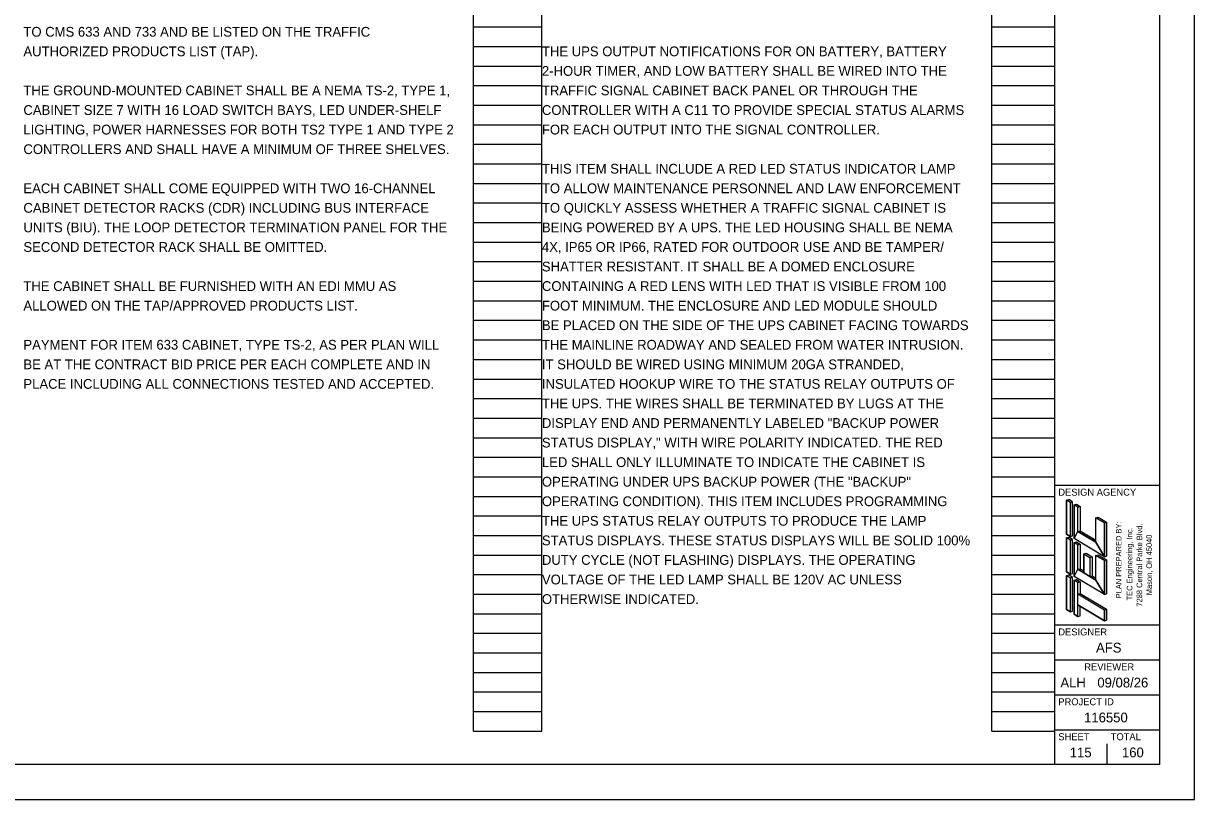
# Model space of a CAD drawing. Extents: x 0 to 34, y 0 to 36.2.
# Drawn here: x 17.24 to 34, y 0 to 11.11 of the extents above; entities that cross this region are included whole.
import ezdxf

# ---------------------------------------------------------------- set-up
doc = ezdxf.new("R2010")
doc.units = 0
for name, color, linetype in [('Default', 7, 'Continuous'), ('SH_Border', 7, 'Continuous'), ('SH_Cut_Line', 7, 'Continuous'), ('SH_Data', 7, 'Continuous'), ('SH_Text', 7, 'Continuous')]:
    doc.layers.add(name, color=color, linetype=linetype)

msp = doc.modelspace()

# ---------------------------------------------------------------- linework, layer by layer
at = {"layer": 'SH_Border'}
for p, q in [((32, 0.5), (32, 21.5)), ((32, 4.5), (33.5, 4.5)), ((32, 2.5), (33.5, 2.5)), ((32, 2), (33.5, 2)), ((32, 1.5), (33.5, 1.5)), ((32, 1), (33.5, 1))]:
    msp.add_line(p, q, dxfattribs=at)
msp.add_lwpolyline([(1.5, 21.5), (33.5, 21.5), (33.5, 0.5), (1.5, 0.5)], close=True, dxfattribs=at)
at = {"layer": 'SH_Cut_Line'}
msp.add_lwpolyline([(0, 0), (34, 0), (34, 22), (0, 22)], close=True, dxfattribs=at)
at = {"layer": 'SH_Data'}
for p, q in [((23.68, 0.98), (23.68, 21.14)), ((24.66, 0.98), (24.66, 21.14)), ((31.1, 0.98), (31.1, 21.14)), ((32, 0.98), (32, 21.14)), ((23.68, 11.06), (24.66, 11.06)), ((31.1, 11.06), (32, 11.06)), ((23.68, 10.78), (24.66, 10.78)), ((31.1, 10.78), (32, 10.78)), ((23.68, 10.5), (24.66, 10.5)), ((31.1, 10.5), (32, 10.5)), ((23.68, 10.22), (24.66, 10.22)), ((31.1, 10.22), (32, 10.22)), ((23.68, 9.94), (24.66, 9.94)), ((31.1, 9.94), (32, 9.94)), ((23.68, 9.66), (24.66, 9.66)), ((31.1, 9.66), (32, 9.66)), ((23.68, 9.38), (24.66, 9.38)), ((31.1, 9.38), (32, 9.38)), ((23.68, 9.1), (24.66, 9.1)), ((31.1, 9.1), (32, 9.1)), ((23.68, 8.82), (24.66, 8.82)), ((31.1, 8.82), (32, 8.82)), ((23.68, 8.54), (24.66, 8.54)), ((31.1, 8.54), (32, 8.54)), ((23.68, 8.26), (24.66, 8.26)), ((31.1, 8.26), (32, 8.26)), ((23.68, 7.98), (24.66, 7.98)), ((31.1, 7.98), (32, 7.98)), ((23.68, 7.7), (24.66, 7.7)), ((31.1, 7.7), (32, 7.7)), ((23.68, 7.42), (24.66, 7.42)), ((31.1, 7.42), (32, 7.42)), ((23.68, 7.14), (24.66, 7.14)), ((31.1, 7.14), (32, 7.14)), ((23.68, 6.86), (24.66, 6.86)), ((31.1, 6.86), (32, 6.86)), ((23.68, 6.58), (24.66, 6.58)), ((31.1, 6.58), (32, 6.58)), ((23.68, 6.3), (24.66, 6.3)), ((31.1, 6.3), (32, 6.3)), ((23.68, 6.02), (24.66, 6.02)), ((31.1, 6.02), (32, 6.02)), ((23.68, 5.74), (24.66, 5.74)), ((31.1, 5.74), (32, 5.74)), ((23.68, 5.46), (24.66, 5.46)), ((31.1, 5.46), (32, 5.46)), ((23.68, 5.18), (24.66, 5.18)), ((31.1, 5.18), (32, 5.18)), ((23.68, 4.9), (24.66, 4.9)), ((31.1, 4.9), (32, 4.9)), ((23.68, 4.62), (24.66, 4.62)), ((31.1, 4.62), (32, 4.62)), ((23.68, 4.34), (24.66, 4.34)), ((31.1, 4.34), (32, 4.34)), ((23.68, 4.06), (24.66, 4.06)), ((31.1, 4.06), (32, 4.06)), ((23.68, 3.78), (24.66, 3.78)), ((31.1, 3.78), (32, 3.78)), ((23.68, 3.5), (24.66, 3.5)), ((31.1, 3.5), (32, 3.5)), ((32.75, 3.5), (32.75, 3.5)), ((23.68, 3.22), (24.66, 3.22)), ((31.1, 3.22), (32, 3.22)), ((23.68, 2.94), (24.66, 2.94)), ((31.1, 2.94), (32, 2.94)), ((23.68, 2.66), (24.66, 2.66)), ((31.1, 2.66), (32, 2.66)), ((23.68, 2.38), (24.66, 2.38)), ((31.1, 2.38), (32, 2.38)), ((23.68, 2.1), (24.66, 2.1)), ((31.1, 2.1), (32, 2.1)), ((23.68, 1.82), (24.66, 1.82)), ((31.1, 1.82), (32, 1.82)), ((23.68, 1.54), (24.66, 1.54)), ((31.1, 1.54), (32, 1.54)), ((23.68, 1.26), (24.66, 1.26)), ((31.1, 1.26), (32, 1.26)), ((23.68, 0.98), (24.66, 0.98)), ((31.1, 0.98), (32, 0.98)), ((32.375, 0.675), (32.375, 0.675)), ((32.75, 0.5), (32.75, 0.8))]:
    msp.add_line(p, q, dxfattribs=at)
at = {"layer": 'SH_Text'}
for p, q in [((32.169, 4.285), (32.201, 4.294)), ((32.169, 3.799), (32.169, 4.285)), ((32.223, 4.253), (32.169, 4.285)), ((32.255, 4.261), (32.201, 4.294)), ((32.223, 4.253), (32.255, 4.261)), ((32.223, 3.767), (32.223, 4.253)), ((32.255, 3.775), (32.255, 4.261)), ((32.277, 4.221), (32.309, 4.229)), ((32.331, 4.188), (32.277, 4.221)), ((32.277, 3.735), (32.277, 4.221)), ((32.309, 4.229), (32.363, 4.196)), ((32.331, 4.188), (32.363, 4.196)), ((32.363, 4.196), (32.363, 3.845)), ((32.331, 3.837), (32.331, 4.188)), ((32.587, 4.034), (32.62, 4.042)), ((32.587, 3.683), (32.587, 4.034)), ((32.709, 3.961), (32.587, 4.034)), ((32.62, 4.042), (32.741, 3.97)), ((32.709, 3.961), (32.741, 3.97)), ((32.709, 3.475), (32.709, 3.961)), ((32.741, 3.97), (32.741, 3.484)), ((32.223, 3.767), (32.169, 3.799)), ((32.169, 3.745), (32.201, 3.754)), ((32.169, 3.259), (32.169, 3.745)), ((32.223, 3.713), (32.169, 3.745)), ((32.255, 3.722), (32.201, 3.754)), ((32.223, 3.767), (32.255, 3.775)), ((32.223, 3.713), (32.255, 3.722)), ((32.223, 3.227), (32.223, 3.713)), ((32.255, 3.236), (32.255, 3.722)), ((32.709, 3.475), (32.277, 3.735)), ((32.277, 3.681), (32.309, 3.689)), ((32.309, 3.689), (32.363, 3.656)), ((32.331, 3.837), (32.363, 3.845)), ((32.587, 3.683), (32.331, 3.837)), ((32.363, 3.845), (32.587, 3.711)), ((32.277, 3.195), (32.277, 3.681)), ((32.331, 3.648), (32.277, 3.681)), ((32.331, 3.648), (32.363, 3.656)), ((32.331, 3.297), (32.331, 3.648)), ((32.363, 3.656), (32.363, 3.305)), ((32.415, 3.519), (32.448, 3.527)), ((32.448, 3.527), (32.535, 3.474)), ((32.415, 3.519), (32.415, 3.247)), ((32.415, 3.519), (32.503, 3.466)), ((32.503, 3.466), (32.535, 3.474)), ((32.503, 3.466), (32.503, 3.194)), ((32.535, 3.474), (32.535, 3.202)), ((32.587, 3.494), (32.62, 3.502)), ((32.587, 3.143), (32.587, 3.494)), ((32.709, 3.421), (32.587, 3.494)), ((32.62, 3.502), (32.741, 3.43)), ((32.709, 3.475), (32.741, 3.484)), ((32.709, 3.421), (32.741, 3.43)), ((32.709, 2.935), (32.709, 3.421)), ((32.741, 3.43), (32.741, 2.944)), ((32.223, 3.227), (32.169, 3.259)), ((32.169, 3.205), (32.201, 3.215)), ((32.169, 2.719), (32.169, 3.205)), ((32.223, 3.173), (32.169, 3.205)), ((32.255, 3.181), (32.201, 3.215)), ((32.223, 3.227), (32.255, 3.236)), ((32.709, 2.935), (32.277, 3.195)), ((32.331, 3.297), (32.363, 3.305)), ((32.415, 3.247), (32.331, 3.297)), ((32.363, 3.305), (32.415, 3.274)), ((32.503, 3.194), (32.535, 3.202)), ((32.587, 3.143), (32.503, 3.194)), ((32.535, 3.202), (32.587, 3.171)), ((32.222, 3.173), (32.255, 3.181)), ((32.223, 2.687), (32.223, 3.173)), ((32.255, 2.695), (32.255, 3.181)), ((32.277, 3.141), (32.309, 3.151)), ((32.331, 3.108), (32.277, 3.141)), ((32.277, 2.655), (32.277, 3.141)), ((32.309, 3.151), (32.363, 3.116)), ((32.331, 3.108), (32.363, 3.116)), ((32.331, 2.944), (32.331, 3.108)), ((32.363, 3.116), (32.363, 2.952)), ((32.331, 2.944), (32.363, 2.952)), ((32.331, 2.944), (32.709, 2.717)), ((32.363, 2.952), (32.741, 2.725)), ((32.709, 2.935), (32.741, 2.944)), ((32.223, 2.687), (32.169, 2.719)), ((32.223, 2.687), (32.255, 2.695)), ((32.331, 2.787), (32.709, 2.56)), ((32.331, 2.622), (32.331, 2.787)), ((32.363, 2.63), (32.363, 2.767)), ((32.709, 2.717), (32.741, 2.725)), ((32.709, 2.56), (32.709, 2.717)), ((32.741, 2.725), (32.741, 2.568)), ((32.331, 2.622), (32.277, 2.655)), ((32.331, 2.622), (32.363, 2.63)), ((32.709, 2.56), (32.741, 2.568))]:
    msp.add_line(p, q, dxfattribs=at)
for points in [[(32.169, 3.799), (32.223, 3.767), (32.223, 4.253), (32.169, 4.285)], [(32.277, 3.735), (32.331, 3.837), (32.331, 4.188), (32.277, 4.221)], [(32.709, 3.475), (32.587, 3.683), (32.587, 4.034), (32.709, 3.961)], [(32.169, 3.259), (32.223, 3.227), (32.223, 3.713), (32.169, 3.745)], [(32.277, 3.735), (32.331, 3.837), (32.587, 3.683), (32.709, 3.475)], [(32.277, 3.195), (32.331, 3.297), (32.331, 3.648), (32.277, 3.681)], [(32.415, 3.247), (32.415, 3.519), (32.503, 3.466), (32.503, 3.194)], [(32.709, 2.935), (32.587, 3.143), (32.587, 3.494), (32.709, 3.421)], [(32.169, 2.719), (32.223, 2.687), (32.223, 3.173), (32.169, 3.205)], [(32.277, 3.195), (32.331, 3.297), (32.587, 3.143), (32.709, 2.935)], [(32.277, 2.655), (32.331, 2.622), (32.331, 3.108), (32.277, 3.141)], [(32.331, 2.787), (32.331, 2.944), (32.709, 2.717), (32.709, 2.56)]]:
    msp.add_lwpolyline(points, close=True, dxfattribs=at)

# ---------------------------------------------------------------- texts
at = {"layer": 'Default'}
for s, p in [('PLAN PREPARED BY:', (32.954, 2.88)), ('TEC Engineering, Inc.', (33.11, 2.851)), ('7288 Central Parke Blvd.', (33.25, 2.762)), ('Mason, OH 45040', (33.39, 2.925))]:
    msp.add_text(s, height=0.08, rotation=90, dxfattribs=at).set_placement(p)
at = {"layer": 'SH_Data'}
for s, height, p in [('DESIGN AGENCY', 0.1, (32.05, 4.35)), ('DESIGNER', 0.1, (32.05, 2.35)), ('AFS', 0.14, (32.59, 2.105)), ('REVIEWER', 0.1, (32.422, 1.85)), ('ALH', 0.14, (32.08, 1.605)), ('09/08/26', 0.14, (32.609, 1.605)), ('PROJECT ID', 0.1, (32.05, 1.35)), ('116550', 0.14, (32.419, 1.105)), ('SHEET', 0.1, (32.05, 0.85)), ('TOTAL', 0.1, (32.8, 0.85)), ('115', 0.14, (32.214, 0.605)), ('160', 0.14, (32.961, 0.605))]:
    msp.add_text(s, height=height, dxfattribs=at).set_placement(p)
at = {"layer": 'SH_Text'}
for s, p in [('TO CMS 633 AND 733 AND BE LISTED ON THE TRAFFIC', (17.24, 10.92)), ('AUTHORIZED PRODUCTS LIST (TAP).', (17.24, 10.64)), ('THE UPS OUTPUT NOTIFICATIONS FOR ON BATTERY, BATTERY', (24.66, 10.64)), ('2-HOUR TIMER, AND LOW BATTERY SHALL BE WIRED INTO THE', (24.66, 10.36)), ('THE GROUND-MOUNTED CABINET SHALL BE A NEMA TS-2, TYPE 1,', (17.24, 10.08)), ('TRAFFIC SIGNAL CABINET BACK PANEL OR THROUGH THE', (24.66, 10.08)), ('CABINET SIZE 7 WITH 16 LOAD SWITCH BAYS, LED UNDER-SHELF', (17.24, 9.8)), ('CONTROLLER WITH A C11 TO PROVIDE SPECIAL STATUS ALARMS', (24.66, 9.8)), ('LIGHTING, POWER HARNESSES FOR BOTH TS2 TYPE 1 AND TYPE 2', (17.24, 9.52)), ('FOR EACH OUTPUT INTO THE SIGNAL CONTROLLER.', (24.66, 9.52)), ('CONTROLLERS AND SHALL HAVE A MINIMUM OF THREE SHELVES.', (17.24, 9.24)), ('THIS ITEM SHALL INCLUDE A RED LED STATUS INDICATOR LAMP', (24.66, 8.96)), ('EACH CABINET SHALL COME EQUIPPED WITH TWO 16-CHANNEL', (17.24, 8.68)), ('TO ALLOW MAINTENANCE PERSONNEL AND LAW ENFORCEMENT', (24.66, 8.68)), ('CABINET DETECTOR RACKS (CDR) INCLUDING BUS INTERFACE', (17.24, 8.4)), ('TO QUICKLY ASSESS WHETHER A TRAFFIC SIGNAL CABINET IS', (24.66, 8.4)), ('UNITS (BIU). THE LOOP DETECTOR TERMINATION PANEL FOR THE', (17.24, 8.12)), ('BEING POWERED BY A UPS. THE LED HOUSING SHALL BE NEMA', (24.66, 8.12)), ('SECOND DETECTOR RACK SHALL BE OMITTED.', (17.24, 7.84)), ('4X, IP65 OR IP66, RATED FOR OUTDOOR USE AND BE TAMPER/', (24.66, 7.84)), ('SHATTER RESISTANT. IT SHALL BE A DOMED ENCLOSURE', (24.66, 7.56)), ('THE CABINET SHALL BE FURNISHED WITH AN EDI MMU AS', (17.24, 7.28)), ('CONTAINING A RED LENS WITH LED THAT IS VISIBLE FROM 100', (24.66, 7.28)), ('ALLOWED ON THE TAP/APPROVED PRODUCTS LIST.', (17.24, 7)), ('FOOT MINIMUM. THE ENCLOSURE AND LED MODULE SHOULD', (24.66, 7)), ('BE PLACED ON THE SIDE OF THE UPS CABINET FACING TOWARDS', (24.66, 6.72)), ('PAYMENT FOR ITEM 633 CABINET, TYPE TS-2, AS PER PLAN WILL', (17.24, 6.44)), ('THE MAINLINE ROADWAY AND SEALED FROM WATER INTRUSION.', (24.66, 6.44)), ('BE AT THE CONTRACT BID PRICE PER EACH COMPLETE AND IN', (17.24, 6.16)), ('IT SHOULD BE WIRED USING MINIMUM 20GA STRANDED,', (24.66, 6.16)), ('PLACE INCLUDING ALL CONNECTIONS TESTED AND ACCEPTED.', (17.24, 5.88)), ('INSULATED HOOKUP WIRE TO THE STATUS RELAY OUTPUTS OF', (24.66, 5.88)), ('THE UPS. THE WIRES SHALL BE TERMINATED BY LUGS AT THE', (24.66, 5.6)), ('DISPLAY END AND PERMANENTLY LABELED "BACKUP POWER', (24.66, 5.32)), ('STATUS DISPLAY," WITH WIRE POLARITY INDICATED. THE RED', (24.66, 5.04)), ('LED SHALL ONLY ILLUMINATE TO INDICATE THE CABINET IS', (24.66, 4.76)), ('OPERATING UNDER UPS BACKUP POWER (THE "BACKUP"', (24.66, 4.48)), ('OPERATING CONDITION). THIS ITEM INCLUDES PROGRAMMING', (24.66, 4.2)), ('THE UPS STATUS RELAY OUTPUTS TO PRODUCE THE LAMP', (24.66, 3.92)), ('STATUS DISPLAYS. THESE STATUS DISPLAYS WILL BE SOLID 100%', (24.66, 3.64)), ('DUTY CYCLE (NOT FLASHING) DISPLAYS. THE OPERATING', (24.66, 3.36)), ('VOLTAGE OF THE LED LAMP SHALL BE 120V AC UNLESS', (24.66, 3.08)), ('OTHERWISE INDICATED.', (24.66, 2.8))]:
    msp.add_text(s, height=0.14, dxfattribs=at).set_placement(p)

doc.saveas('drawing.dxf')
